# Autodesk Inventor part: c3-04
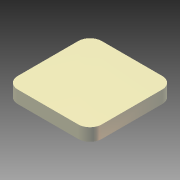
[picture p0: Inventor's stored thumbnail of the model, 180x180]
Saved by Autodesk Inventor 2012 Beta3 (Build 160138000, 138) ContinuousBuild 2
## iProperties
Created: 2010-11
Part Number: c3-04
Material: Cast Iron
Document SubType Name: Modeling
Designer: Beta-8540w
Density: 7.25 g/cm^3
Mass: 1087.5 g
Surface Area: 260 cm^2
Volume: 150 cm^3
Author: Beta-8540w
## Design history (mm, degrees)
sketch "Sketch1"
  geometry: L1 (-50, -50)-(50, -50); L2 (50, -50)-(50, 50); L3 (50, 50)-(-50, 50); L4 (-50, 50)-(-50, -50); 3 further points
  constraints: 8 end point, 3 perpendicular, 2 midpoint, 1 horizontal, 1 horizontal alignment, 1 parallel, 1 vertical alignment
  dimensions: "Width" = 100 distance of L1.start L1.end
extrude "Extrusion1" new body sketch "Sketch1" distance "d3" = 15; taper "d4" = 0 deg
fillet "Fillet1" dims "d5" = 14
body "Solid1"
